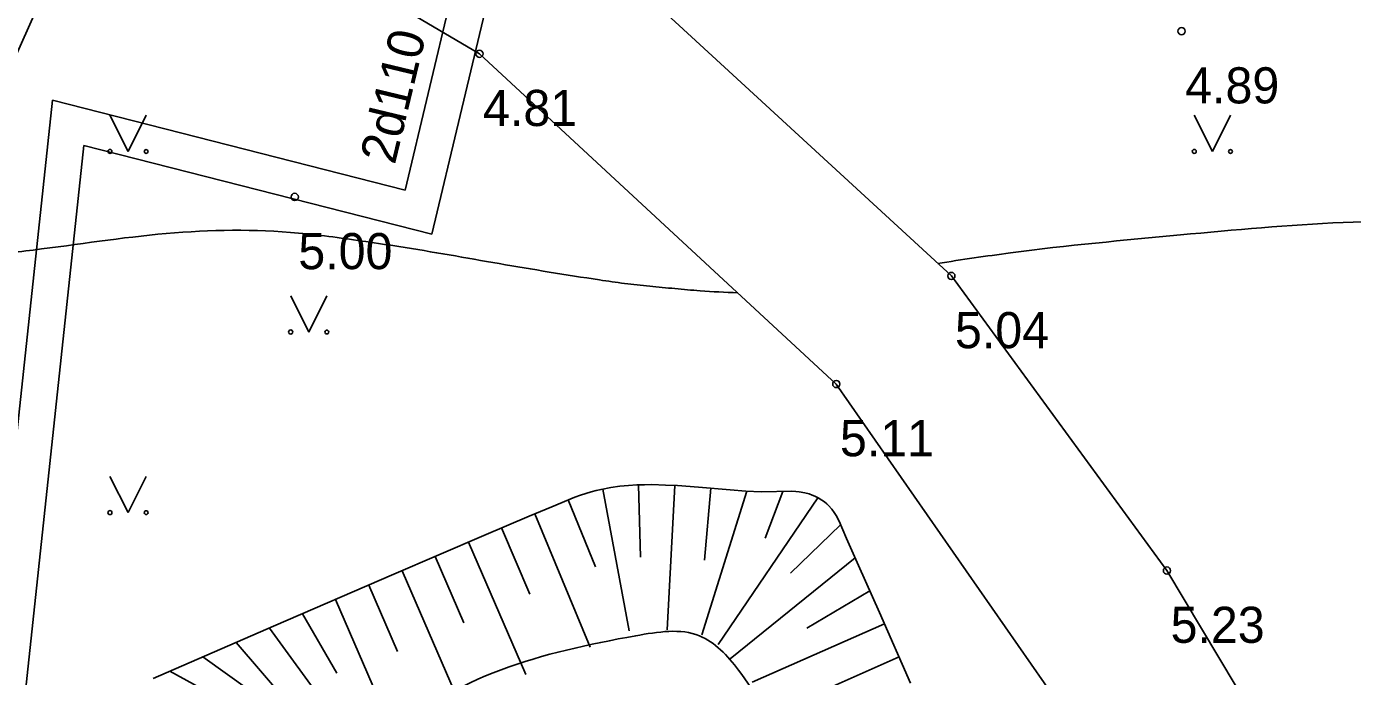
# Model space of a CAD drawing. Extents: x 519536 to 519949, y 326041 to 326519.
# Drawn here: x 519691.1 to 519709.44, y 326165.23 to 326174.23 of the extents above; entities that cross this region are included whole.
import ezdxf

# ---------------------------------------------------------------- set-up
doc = ezdxf.new("R2010")
doc.units = 0
for name, color, linetype in [('CELI_CMAL_####_####_#', 7, 'Continuous'), ('ELEK_VADV_ZSPR_####_#', 7, 'Continuous'), ('RELJ_AATZ_####_TKST_#', 7, 'Continuous'), ('RELJ_ELEM_####_####_#', 7, 'Continuous'), ('RELJ_HORZ_PAMT_####_#', 7, 'Continuous'), ('RELJ_NOGA_####_####_#', 7, 'Continuous'), ('RELJ_NOGL_####_####_#', 7, 'Continuous'), ('SILT_VADP_UDEN_####_#', 7, 'Continuous'), ('SILT_VADP_UDEN_TKST_#', 7, 'Continuous'), ('TERT_ELEM_####_####_#', 7, 'Continuous')]:
    doc.layers.add(name, color=color, linetype=linetype)

msp = doc.modelspace()

# ---------------------------------------------------------------- linework, layer by layer
at = {"layer": 'CELI_CMAL_####_####_#'}
for points in [[(519725.6, 326145.595), (519722.795, 326148.479), (519717.487, 326152.615), (519712.383, 326157.466), (519706.872, 326166.697), (519703.889, 326170.776), (519699.04, 326175.245), (519687.684, 326181.825), (519678.238, 326187.413), (519670.804, 326192.027), (519670.048, 326192.682), (519664.865, 326189.411), (519662.65, 326188.197)], [(519662.737, 326185.995), (519665.714, 326187.6), (519670.496, 326188.216), (519674.588, 326187.052), (519687.563, 326179.623), (519697.361, 326173.852), (519702.298, 326169.28), (519707.151, 326162.302), (519711.634, 326155.197), (519719.91, 326147.956), (519722.688, 326145.028)]]:
    msp.add_lwpolyline(points, dxfattribs=at)
at = {"layer": 'ELEK_VADV_ZSPR_####_#'}
msp.add_line((519666.72, 326119.401), (519722.531, 326244.78), dxfattribs=at)
at = {"layer": 'RELJ_ELEM_####_####_#'}
for centre in [(519707.074, 326174.165), (519697.361, 326173.852), (519694.806, 326171.87), (519703.889, 326170.776), (519702.298, 326169.28), (519706.872, 326166.697)]:
    msp.add_circle(centre, 0.05, dxfattribs=at)
at = {"layer": 'RELJ_HORZ_PAMT_####_#'}
for points in [[(519703.7, 326170.95), (519704.708, 326171.096), (519707.058, 326171.344), (519709.307, 326171.516), (519711.53, 326171.484), (519712.642, 326171.373), (519713.753, 326171.213), (519716.272, 326170.744), (519718.755, 326170.156), (519720.711, 326169.596), (519722.223, 326169.07), (519724.566, 326168.272), (519726.32, 326167.713), (519726.38, 326167.694)], [(519690.359, 326171.04), (519691.188, 326171.135), (519693.029, 326171.363), (519694.86, 326171.37), (519695.335, 326171.316)], [(519695.335, 326171.316), (519696.248, 326171.183), (519697.634, 326170.947), (519699.022, 326170.722), (519699.369, 326170.673), (519699.716, 326170.634), (519700.065, 326170.601), (519700.413, 326170.571), (519700.934, 326170.543)]]:
    msp.add_spline(points, degree=3, dxfattribs=at)
at = {"layer": 'RELJ_NOGA_####_####_#'}
for p, q in [((519699.562, 326167.884), (519699.591, 326166.884)), ((519700.062, 326167.876), (519699.958, 326165.878)), ((519699.066, 326167.826), (519699.434, 326165.861)), ((519701.059, 326167.798), (519700.436, 326165.81)), ((519700.56, 326167.837), (519700.474, 326166.841)), ((519702.044, 326167.706), (519700.663, 326165.673)), ((519701.558, 326167.793), (519701.315, 326167.148)), ((519698.59, 326167.675), (519698.968, 326166.749)), ((519698.128, 326167.484), (519698.895, 326165.637)), ((519702.357, 326167.331), (519701.663, 326166.662)), ((519697.667, 326167.289), (519698.058, 326166.369)), ((519697.208, 326167.093), (519698.002, 326165.257)), ((519696.749, 326166.894), (519697.146, 326165.976)), ((519702.56, 326166.873), (519700.83, 326165.475)), ((519696.29, 326166.695), (519697.085, 326164.86)), ((519695.831, 326166.497), (519696.229, 326165.579)), ((519702.763, 326166.417), (519701.891, 326165.901)), ((519695.372, 326166.298), (519696.167, 326164.463)), ((519694.914, 326166.099), (519695.389, 326165.276)), ((519694.455, 326165.901), (519695.817, 326164.04)), ((519702.966, 326165.959), (519701.135, 326165.153)), ((519693.996, 326165.702), (519694.671, 326164.915)), ((519693.537, 326165.503), (519695.8, 326163.885)), ((519703.167, 326165.502), (519702.252, 326165.099)), ((519693.078, 326165.304), (519694.106, 326164.744))]:
    msp.add_line(p, q, dxfattribs=at)
msp.add_lwpolyline([(519692.849, 326165.205), (519694.512, 326165.926), (519696.176, 326166.646), (519697.422, 326167.185), (519698.048, 326167.451), (519698.364, 326167.582), (519698.682, 326167.712), (519698.758, 326167.741), (519698.832, 326167.766), (519698.905, 326167.788), (519698.975, 326167.806), (519699.044, 326167.822), (519699.178, 326167.847), (519699.305, 326167.865), (519699.425, 326167.876), (519699.539, 326167.883), (519699.645, 326167.886), (519699.746, 326167.887), (519699.935, 326167.882), (519700.101, 326167.873), (519700.393, 326167.851), (519700.83, 326167.814), (519701.048, 326167.798), (519701.263, 326167.789), (519701.684, 326167.795), (519701.737, 326167.792), (519701.782, 326167.787), (519701.862, 326167.773), (519701.922, 326167.758), (519701.966, 326167.742), (519701.999, 326167.728), (519702.049, 326167.704), (519702.098, 326167.674), (519702.134, 326167.648), (519702.165, 326167.622), (519702.192, 326167.597), (519702.236, 326167.547), (519702.27, 326167.501), (519702.296, 326167.458), (519702.336, 326167.381), (519702.439, 326167.141), (519702.607, 326166.77), (519702.896, 326166.118), (519703.326, 326165.141)], dxfattribs=at)
msp.add_lwpolyline([(519692.849, 326165.205), (519694.512, 326165.926), (519696.176, 326166.646), (519697.422, 326167.185), (519698.048, 326167.451), (519698.364, 326167.582), (519698.682, 326167.712), (519698.758, 326167.741), (519698.832, 326167.766), (519698.905, 326167.788), (519698.975, 326167.806), (519699.044, 326167.822), (519699.178, 326167.847), (519699.305, 326167.865), (519699.425, 326167.876), (519699.539, 326167.883), (519699.645, 326167.886), (519699.746, 326167.887), (519699.935, 326167.882), (519700.101, 326167.873), (519700.393, 326167.851), (519700.83, 326167.814), (519701.048, 326167.798), (519701.263, 326167.789), (519701.684, 326167.795), (519701.737, 326167.792), (519701.782, 326167.787), (519701.862, 326167.773), (519701.922, 326167.758), (519701.966, 326167.742), (519701.999, 326167.728), (519702.049, 326167.704), (519702.098, 326167.674), (519702.134, 326167.648), (519702.165, 326167.622), (519702.192, 326167.597), (519702.236, 326167.547), (519702.27, 326167.501), (519702.296, 326167.458), (519702.336, 326167.381), (519702.439, 326167.141), (519702.607, 326166.77), (519702.896, 326166.118), (519703.326, 326165.141)], dxfattribs=at)
msp.add_lwpolyline([(519692.849, 326165.205), (519694.512, 326165.926), (519696.176, 326166.646), (519697.422, 326167.185), (519698.048, 326167.451), (519698.364, 326167.582), (519698.682, 326167.712), (519698.758, 326167.741), (519698.832, 326167.766), (519698.905, 326167.788), (519698.975, 326167.806), (519699.044, 326167.822), (519699.178, 326167.847), (519699.305, 326167.865), (519699.425, 326167.876), (519699.539, 326167.883), (519699.645, 326167.886), (519699.746, 326167.887), (519699.935, 326167.882), (519700.101, 326167.873), (519700.393, 326167.851), (519700.83, 326167.814), (519701.048, 326167.798), (519701.263, 326167.789), (519701.684, 326167.795), (519701.737, 326167.792), (519701.782, 326167.787), (519701.862, 326167.773), (519701.922, 326167.758), (519701.966, 326167.742), (519701.999, 326167.728), (519702.049, 326167.704), (519702.098, 326167.674), (519702.134, 326167.648), (519702.165, 326167.622), (519702.192, 326167.597), (519702.236, 326167.547), (519702.27, 326167.501), (519702.296, 326167.458), (519702.336, 326167.381), (519702.439, 326167.141), (519702.607, 326166.77), (519702.896, 326166.118), (519703.326, 326165.141)], dxfattribs=at)
msp.add_lwpolyline([(519692.849, 326165.205), (519694.512, 326165.926), (519696.176, 326166.646), (519697.422, 326167.185), (519698.048, 326167.451), (519698.364, 326167.582), (519698.682, 326167.712), (519698.758, 326167.741), (519698.832, 326167.766), (519698.905, 326167.788), (519698.975, 326167.806), (519699.044, 326167.822), (519699.178, 326167.847), (519699.305, 326167.865), (519699.425, 326167.876), (519699.539, 326167.883), (519699.645, 326167.886), (519699.746, 326167.887), (519699.935, 326167.882), (519700.101, 326167.873), (519700.393, 326167.851), (519700.83, 326167.814), (519701.048, 326167.798), (519701.263, 326167.789), (519701.684, 326167.795), (519701.737, 326167.792), (519701.782, 326167.787), (519701.862, 326167.773), (519701.922, 326167.758), (519701.966, 326167.742), (519701.999, 326167.728), (519702.049, 326167.704), (519702.098, 326167.674), (519702.134, 326167.648), (519702.165, 326167.622), (519702.192, 326167.597), (519702.236, 326167.547), (519702.27, 326167.501), (519702.296, 326167.458), (519702.336, 326167.381), (519702.439, 326167.141), (519702.607, 326166.77), (519702.896, 326166.118), (519703.326, 326165.141)], dxfattribs=at)
msp.add_lwpolyline([(519692.849, 326165.205), (519694.512, 326165.926), (519696.176, 326166.646), (519697.422, 326167.185), (519698.048, 326167.451), (519698.364, 326167.582), (519698.682, 326167.712), (519698.758, 326167.741), (519698.832, 326167.766), (519698.905, 326167.788), (519698.975, 326167.806), (519699.044, 326167.822), (519699.178, 326167.847), (519699.305, 326167.865), (519699.425, 326167.876), (519699.539, 326167.883), (519699.645, 326167.886), (519699.746, 326167.887), (519699.935, 326167.882), (519700.101, 326167.873), (519700.393, 326167.851), (519700.83, 326167.814), (519701.048, 326167.798), (519701.263, 326167.789), (519701.684, 326167.795), (519701.737, 326167.792), (519701.782, 326167.787), (519701.862, 326167.773), (519701.922, 326167.758), (519701.966, 326167.742), (519701.999, 326167.728), (519702.049, 326167.704), (519702.098, 326167.674), (519702.134, 326167.648), (519702.165, 326167.622), (519702.192, 326167.597), (519702.236, 326167.547), (519702.27, 326167.501), (519702.296, 326167.458), (519702.336, 326167.381), (519702.439, 326167.141), (519702.607, 326166.77), (519702.896, 326166.118), (519703.326, 326165.141)], dxfattribs=at)
msp.add_lwpolyline([(519692.849, 326165.205), (519694.512, 326165.926), (519696.176, 326166.646), (519697.422, 326167.185), (519698.048, 326167.451), (519698.364, 326167.582), (519698.682, 326167.712), (519698.758, 326167.741), (519698.832, 326167.766), (519698.905, 326167.788), (519698.975, 326167.806), (519699.044, 326167.822), (519699.178, 326167.847), (519699.305, 326167.865), (519699.425, 326167.876), (519699.539, 326167.883), (519699.645, 326167.886), (519699.746, 326167.887), (519699.935, 326167.882), (519700.101, 326167.873), (519700.393, 326167.851), (519700.83, 326167.814), (519701.048, 326167.798), (519701.263, 326167.789), (519701.684, 326167.795), (519701.737, 326167.792), (519701.782, 326167.787), (519701.862, 326167.773), (519701.922, 326167.758), (519701.966, 326167.742), (519701.999, 326167.728), (519702.049, 326167.704), (519702.098, 326167.674), (519702.134, 326167.648), (519702.165, 326167.622), (519702.192, 326167.597), (519702.236, 326167.547), (519702.27, 326167.501), (519702.296, 326167.458), (519702.336, 326167.381), (519702.439, 326167.141), (519702.607, 326166.77), (519702.896, 326166.118), (519703.326, 326165.141)], dxfattribs=at)
msp.add_lwpolyline([(519692.849, 326165.205), (519694.512, 326165.926), (519696.176, 326166.646), (519697.422, 326167.185), (519698.048, 326167.451), (519698.364, 326167.582), (519698.682, 326167.712), (519698.758, 326167.741), (519698.832, 326167.766), (519698.905, 326167.788), (519698.975, 326167.806), (519699.044, 326167.822), (519699.178, 326167.847), (519699.305, 326167.865), (519699.425, 326167.876), (519699.539, 326167.883), (519699.645, 326167.886), (519699.746, 326167.887), (519699.935, 326167.882), (519700.101, 326167.873), (519700.393, 326167.851), (519700.83, 326167.814), (519701.048, 326167.798), (519701.263, 326167.789), (519701.684, 326167.795), (519701.737, 326167.792), (519701.782, 326167.787), (519701.862, 326167.773), (519701.922, 326167.758), (519701.966, 326167.742), (519701.999, 326167.728), (519702.049, 326167.704), (519702.098, 326167.674), (519702.134, 326167.648), (519702.165, 326167.622), (519702.192, 326167.597), (519702.236, 326167.547), (519702.27, 326167.501), (519702.296, 326167.458), (519702.336, 326167.381), (519702.439, 326167.141), (519702.607, 326166.77), (519702.896, 326166.118), (519703.326, 326165.141)], dxfattribs=at)
msp.add_lwpolyline([(519692.849, 326165.205), (519694.512, 326165.926), (519696.176, 326166.646), (519697.422, 326167.185), (519698.048, 326167.451), (519698.364, 326167.582), (519698.682, 326167.712), (519698.758, 326167.741), (519698.832, 326167.766), (519698.905, 326167.788), (519698.975, 326167.806), (519699.044, 326167.822), (519699.178, 326167.847), (519699.305, 326167.865), (519699.425, 326167.876), (519699.539, 326167.883), (519699.645, 326167.886), (519699.746, 326167.887), (519699.935, 326167.882), (519700.101, 326167.873), (519700.393, 326167.851), (519700.83, 326167.814), (519701.048, 326167.798), (519701.263, 326167.789), (519701.684, 326167.795), (519701.737, 326167.792), (519701.782, 326167.787), (519701.862, 326167.773), (519701.922, 326167.758), (519701.966, 326167.742), (519701.999, 326167.728), (519702.049, 326167.704), (519702.098, 326167.674), (519702.134, 326167.648), (519702.165, 326167.622), (519702.192, 326167.597), (519702.236, 326167.547), (519702.27, 326167.501), (519702.296, 326167.458), (519702.336, 326167.381), (519702.439, 326167.141), (519702.607, 326166.77), (519702.896, 326166.118), (519703.326, 326165.141)], dxfattribs=at)
msp.add_lwpolyline([(519692.849, 326165.205), (519694.512, 326165.926), (519696.176, 326166.646), (519697.422, 326167.185), (519698.048, 326167.451), (519698.364, 326167.582), (519698.682, 326167.712), (519698.758, 326167.741), (519698.832, 326167.766), (519698.905, 326167.788), (519698.975, 326167.806), (519699.044, 326167.822), (519699.178, 326167.847), (519699.305, 326167.865), (519699.425, 326167.876), (519699.539, 326167.883), (519699.645, 326167.886), (519699.746, 326167.887), (519699.935, 326167.882), (519700.101, 326167.873), (519700.393, 326167.851), (519700.83, 326167.814), (519701.048, 326167.798), (519701.263, 326167.789), (519701.684, 326167.795), (519701.737, 326167.792), (519701.782, 326167.787), (519701.862, 326167.773), (519701.922, 326167.758), (519701.966, 326167.742), (519701.999, 326167.728), (519702.049, 326167.704), (519702.098, 326167.674), (519702.134, 326167.648), (519702.165, 326167.622), (519702.192, 326167.597), (519702.236, 326167.547), (519702.27, 326167.501), (519702.296, 326167.458), (519702.336, 326167.381), (519702.439, 326167.141), (519702.607, 326166.77), (519702.896, 326166.118), (519703.326, 326165.141)], dxfattribs=at)
msp.add_lwpolyline([(519692.849, 326165.205), (519694.512, 326165.926), (519696.176, 326166.646), (519697.422, 326167.185), (519698.048, 326167.451), (519698.364, 326167.582), (519698.682, 326167.712), (519698.758, 326167.741), (519698.832, 326167.766), (519698.905, 326167.788), (519698.975, 326167.806), (519699.044, 326167.822), (519699.178, 326167.847), (519699.305, 326167.865), (519699.425, 326167.876), (519699.539, 326167.883), (519699.645, 326167.886), (519699.746, 326167.887), (519699.935, 326167.882), (519700.101, 326167.873), (519700.393, 326167.851), (519700.83, 326167.814), (519701.048, 326167.798), (519701.263, 326167.789), (519701.684, 326167.795), (519701.737, 326167.792), (519701.782, 326167.787), (519701.862, 326167.773), (519701.922, 326167.758), (519701.966, 326167.742), (519701.999, 326167.728), (519702.049, 326167.704), (519702.098, 326167.674), (519702.134, 326167.648), (519702.165, 326167.622), (519702.192, 326167.597), (519702.236, 326167.547), (519702.27, 326167.501), (519702.296, 326167.458), (519702.336, 326167.381), (519702.439, 326167.141), (519702.607, 326166.77), (519702.896, 326166.118), (519703.326, 326165.141)], dxfattribs=at)
msp.add_lwpolyline([(519692.849, 326165.205), (519694.512, 326165.926), (519696.176, 326166.646), (519697.422, 326167.185), (519698.048, 326167.451), (519698.364, 326167.582), (519698.682, 326167.712), (519698.758, 326167.741), (519698.832, 326167.766), (519698.905, 326167.788), (519698.975, 326167.806), (519699.044, 326167.822), (519699.178, 326167.847), (519699.305, 326167.865), (519699.425, 326167.876), (519699.539, 326167.883), (519699.645, 326167.886), (519699.746, 326167.887), (519699.935, 326167.882), (519700.101, 326167.873), (519700.393, 326167.851), (519700.83, 326167.814), (519701.048, 326167.798), (519701.263, 326167.789), (519701.684, 326167.795), (519701.737, 326167.792), (519701.782, 326167.787), (519701.862, 326167.773), (519701.922, 326167.758), (519701.966, 326167.742), (519701.999, 326167.728), (519702.049, 326167.704), (519702.098, 326167.674), (519702.134, 326167.648), (519702.165, 326167.622), (519702.192, 326167.597), (519702.236, 326167.547), (519702.27, 326167.501), (519702.296, 326167.458), (519702.336, 326167.381), (519702.439, 326167.141), (519702.607, 326166.77), (519702.896, 326166.118), (519703.326, 326165.141)], dxfattribs=at)
msp.add_lwpolyline([(519692.849, 326165.205), (519694.512, 326165.926), (519696.176, 326166.646), (519697.422, 326167.185), (519698.048, 326167.451), (519698.364, 326167.582), (519698.682, 326167.712), (519698.758, 326167.741), (519698.832, 326167.766), (519698.905, 326167.788), (519698.975, 326167.806), (519699.044, 326167.822), (519699.178, 326167.847), (519699.305, 326167.865), (519699.425, 326167.876), (519699.539, 326167.883), (519699.645, 326167.886), (519699.746, 326167.887), (519699.935, 326167.882), (519700.101, 326167.873), (519700.393, 326167.851), (519700.83, 326167.814), (519701.048, 326167.798), (519701.263, 326167.789), (519701.684, 326167.795), (519701.737, 326167.792), (519701.782, 326167.787), (519701.862, 326167.773), (519701.922, 326167.758), (519701.966, 326167.742), (519701.999, 326167.728), (519702.049, 326167.704), (519702.098, 326167.674), (519702.134, 326167.648), (519702.165, 326167.622), (519702.192, 326167.597), (519702.236, 326167.547), (519702.27, 326167.501), (519702.296, 326167.458), (519702.336, 326167.381), (519702.439, 326167.141), (519702.607, 326166.77), (519702.896, 326166.118), (519703.326, 326165.141)], dxfattribs=at)
at = {"layer": 'RELJ_NOGL_####_####_#'}
msp.add_spline([(519695.695, 326163.347), (519695.83, 326164.027), (519696.101, 326164.367), (519699.523, 326165.795), (519700.404, 326165.795), (519700.946, 326165.319), (519701.522, 326164.333), (519702.233, 326162.667), (519702.64, 326161.306), (519702.301, 326160.864), (519701.014, 326160.388), (519698.507, 326159.334), (519697.999, 326159.232), (519697.321, 326159.198), (519697.05, 326159.436), (519695.721, 326163.139)], degree=3, dxfattribs=at)
at = {"layer": 'SILT_VADP_UDEN_####_#'}
for p, q in [((519696.701, 326171.354), (519700.067, 326185.473)), ((519696.333, 326171.964), (519699.455, 326185.059)), ((519691.454, 326173.209), (519696.333, 326171.964)), ((519691.89, 326172.581), (519696.701, 326171.354))]:
    msp.add_line(p, q, dxfattribs=at)
for points in [[(519687.958, 326140.524), (519691.454, 326173.209)], [(519688.487, 326140.773), (519691.89, 326172.581)]]:
    msp.add_lwpolyline(points, dxfattribs=at)
at = {"layer": 'TERT_ELEM_####_####_#'}
for p, q in [((519692.25, 326173), (519692.5, 326172.5)), ((519692.5, 326172.5), (519692.75, 326173)), ((519707.25, 326173), (519707.5, 326172.5)), ((519707.5, 326172.5), (519707.75, 326173)), ((519694.75, 326170.5), (519695, 326170)), ((519695, 326170), (519695.25, 326170.5)), ((519692.25, 326168), (519692.5, 326167.5)), ((519692.5, 326167.5), (519692.75, 326168))]:
    msp.add_line(p, q, dxfattribs=at)
for centre, radius in [((519692.25, 326172.5), 0.028), ((519692.75, 326172.5), 0.0263), ((519707.25, 326172.5), 0.028), ((519707.75, 326172.5), 0.0263), ((519694.75, 326170), 0.028), ((519695.25, 326170), 0.0263), ((519692.25, 326167.5), 0.028), ((519692.75, 326167.5), 0.0263)]:
    msp.add_circle(centre, radius, dxfattribs=at)

# ---------------------------------------------------------------- texts
at = {"layer": 'RELJ_AATZ_####_TKST_#'}
for s, p in [('4.89', (519707.124, 326173.165)), ('4.81', (519697.411, 326172.852)), ('5.00', (519694.856, 326170.87)), ('5.04', (519703.939, 326169.776)), ('5.11', (519702.348, 326168.28)), ('5.23', (519706.922, 326165.697))]:
    msp.add_text(s, height=0.5, dxfattribs=at).set_placement(p)
at = {"layer": 'SILT_VADP_UDEN_TKST_#'}
msp.add_text('2d110', height=0.5, rotation=76.4804, dxfattribs=at).set_placement((519696.19, 326172.305))

doc.saveas('drawing.dxf')
